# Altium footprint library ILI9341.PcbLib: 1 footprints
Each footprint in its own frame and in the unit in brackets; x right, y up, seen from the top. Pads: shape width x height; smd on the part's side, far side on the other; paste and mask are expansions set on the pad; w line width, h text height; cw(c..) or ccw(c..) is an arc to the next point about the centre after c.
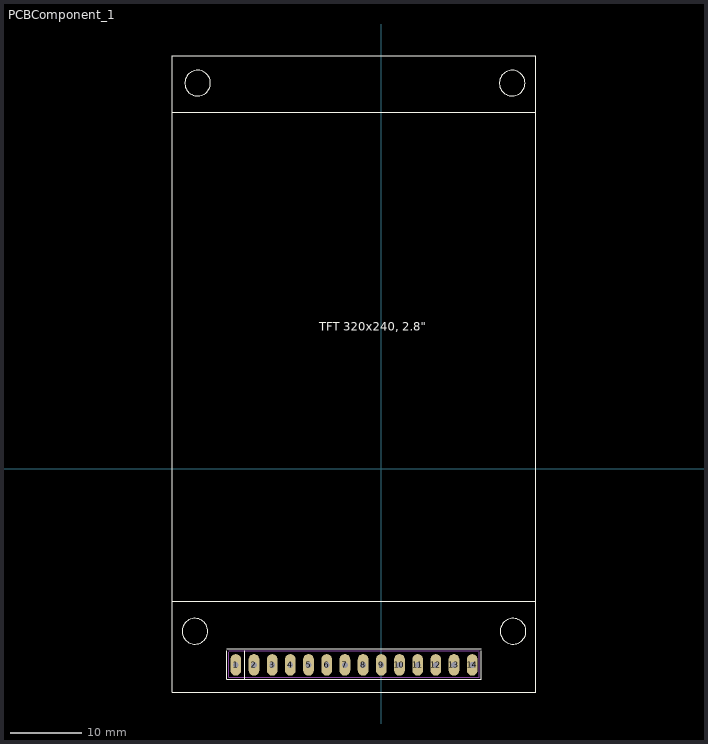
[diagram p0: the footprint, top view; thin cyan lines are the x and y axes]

## PCBComponent_1 [mm]
pads (14):
  rrect100% 1.5x3 hole 0.8: 1(-20.32,-27.432) 2(-17.78,-27.432) 3(-15.24,-27.432) 4(-12.7,-27.432) 5(-10.16,-27.432) 6(-7.62,-27.432) 7(-5.08,-27.432) 8(-2.54,-27.432) 9(0,-27.432) 10(2.54,-27.432) 11(5.08,-27.432) 12(7.62,-27.432) 13(10.16,-27.432) 14(12.7,-27.432)
Top Overlay:
  circle w0.12: c-25.654,53.848 r1.796
  circle w0.12: c-26.035,-22.733 r1.796
  circle w0.12: c18.288,53.848 r1.796
  circle w0.12: c18.415,-22.733 r1.796
  lines w0.12: -29.21,-18.542 21.59,-18.542 ; -29.21,49.784 21.59,49.784 ; -21.57,-25.432 -21.57,-29.432 13.95,-29.432 13.95,-25.432 ; -21.57,-25.178 13.95,-25.178 ; -19.05,-29.432 -19.05,-25.432 ; -29.21,-31.242 -29.21,57.658 21.59,57.658 21.59,-31.242 -29.21,-31.242
  text "TFT 320x240, 2.8\"" at -8.642,18.856 h2
Mechanical 4:
  lines w0.05: -21.32,-25.682 -21.32,-29.182 13.7,-29.182 13.7,-25.682 ; -21.32,-25.428 13.7,-25.428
